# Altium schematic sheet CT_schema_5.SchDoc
size 143 x 123 mm
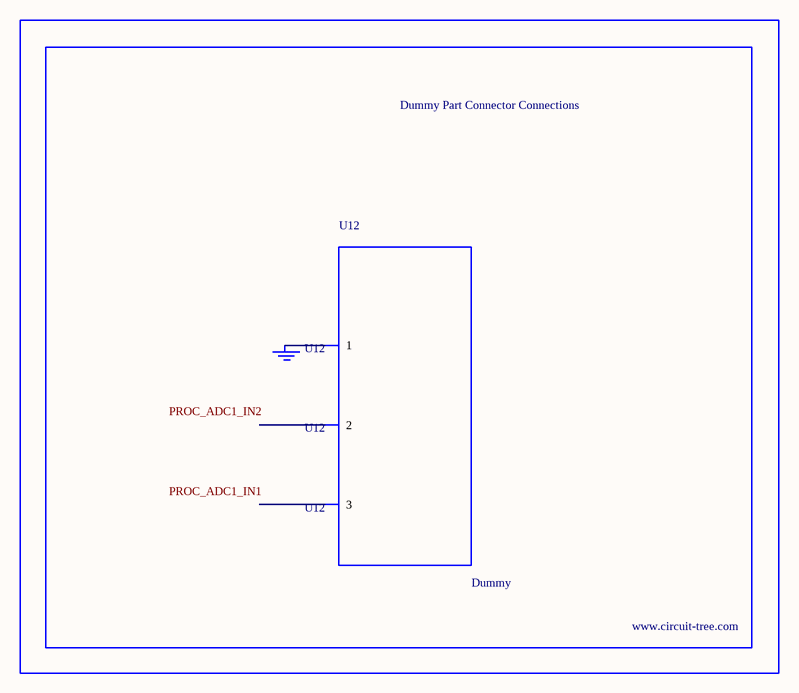
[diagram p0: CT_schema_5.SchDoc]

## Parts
BORDER4  (no value)
GND_INSTANCE_4_0  (no value)
U12  Dummy  [DUMMY_PACKAGE_111]

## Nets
NetGND_INSTANCE_4_0_0: GND_INSTANCE_4_0.0(GND) U12.1

Not connected (* = marked no-connect by the designer): U12 2 3

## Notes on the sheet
- Labels drawn without touching a wire or pin: PROC_ADC1_IN1, PROC_ADC1_IN2

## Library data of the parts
BORDER4 = BORDER_PAGE4
GND_INSTANCE_4_0 = GND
